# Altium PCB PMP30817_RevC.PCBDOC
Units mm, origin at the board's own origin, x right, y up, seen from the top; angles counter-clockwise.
Board outline 75.77 x 49.68 mm, 2 copper layers (Top Layer, Bottom Layer), stack 1.575 mm thick; 52 components, 29 nets, 115 pads, 20 vias.
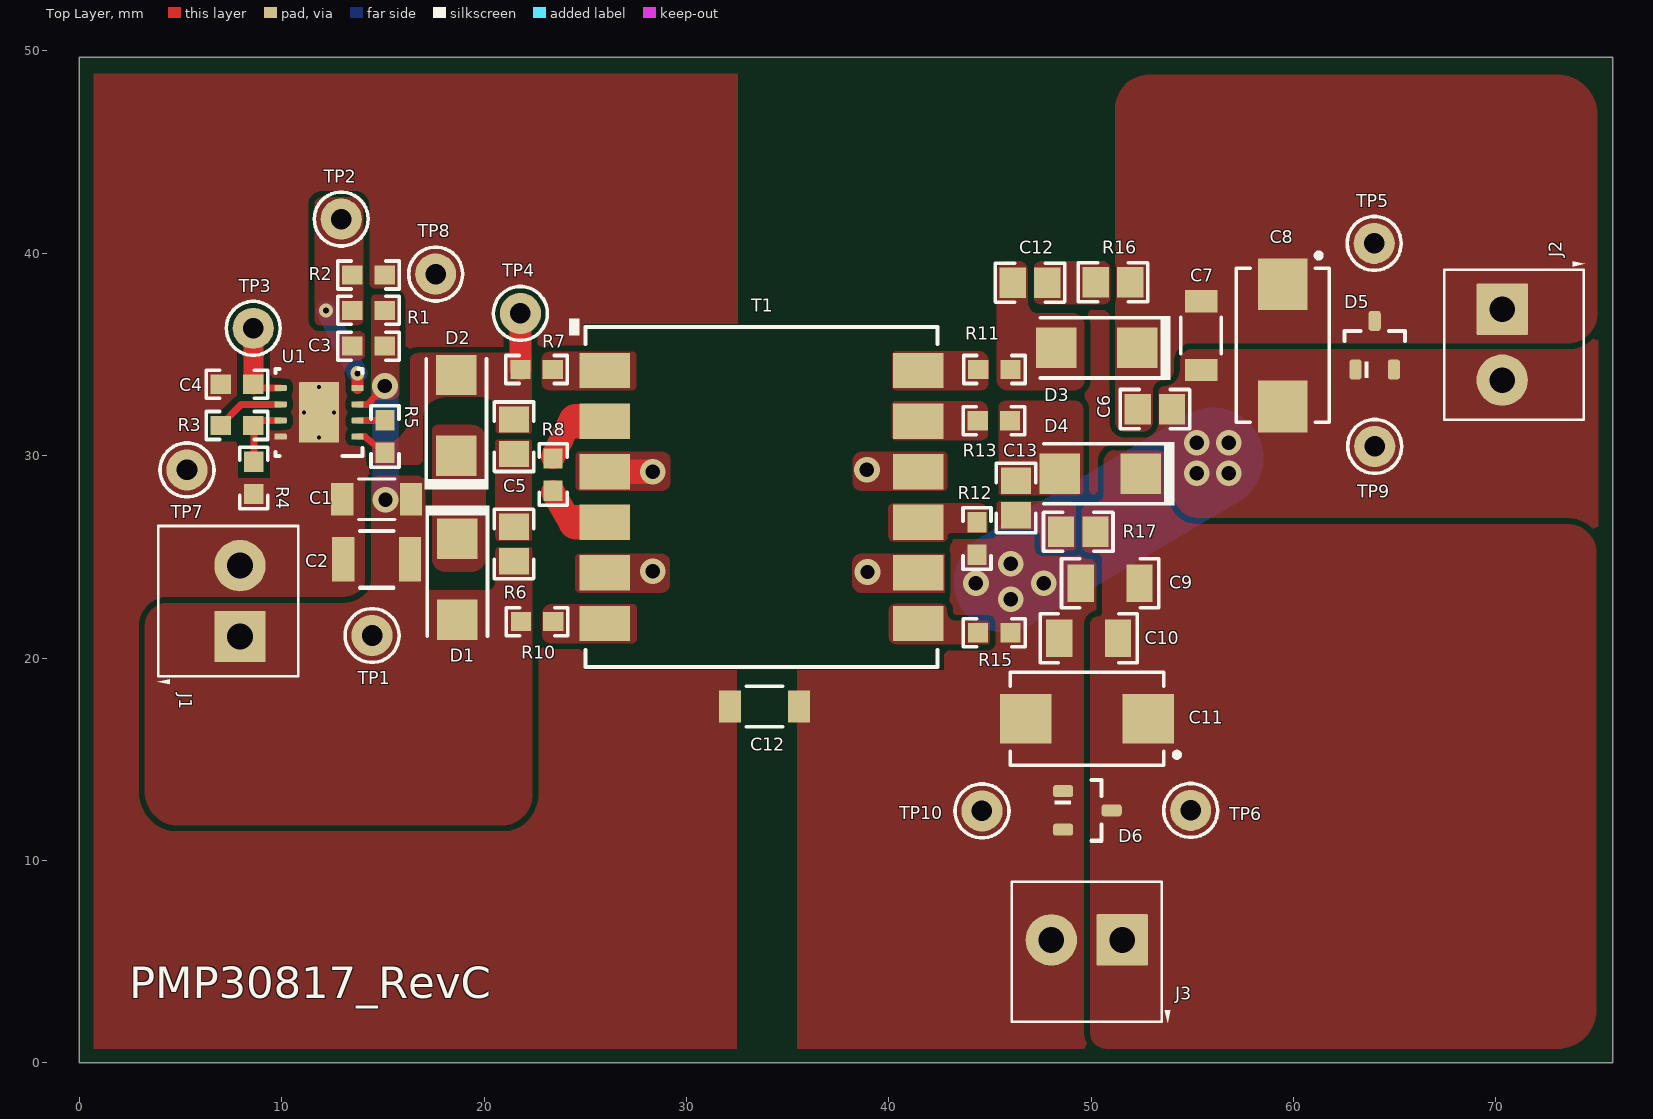
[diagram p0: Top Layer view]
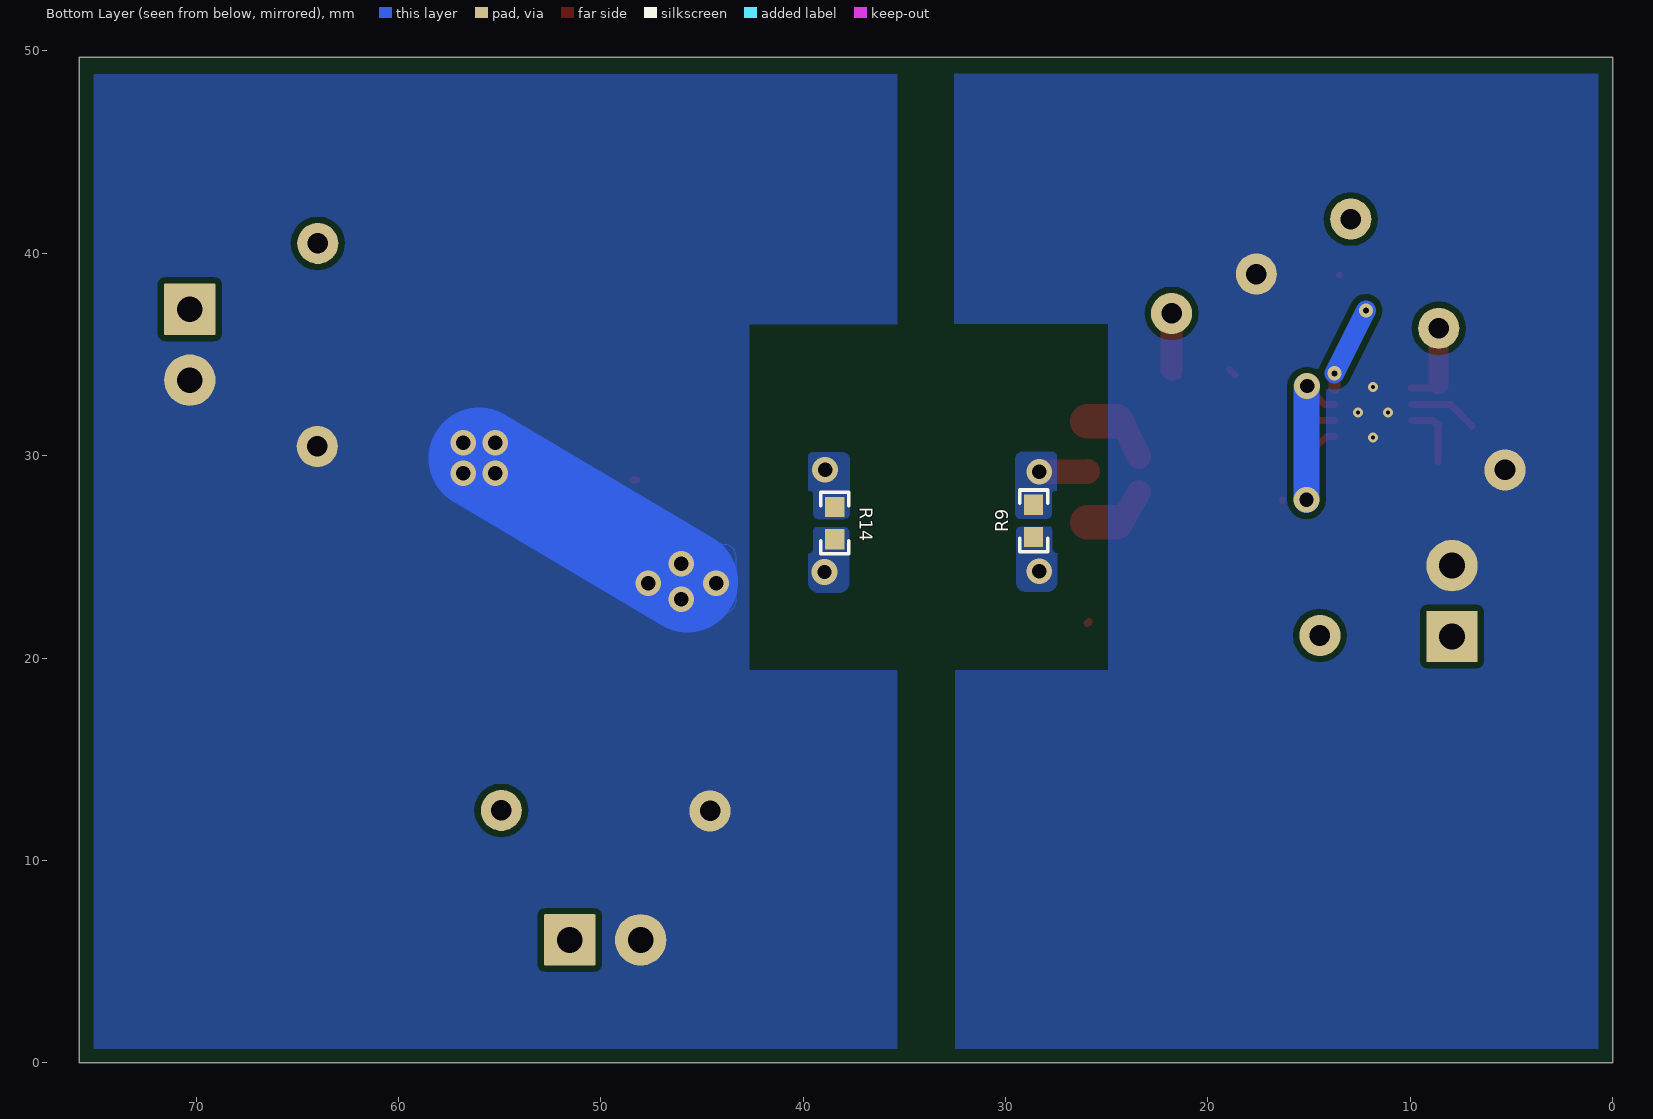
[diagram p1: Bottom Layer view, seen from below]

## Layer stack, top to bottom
Top Solder: solder mask 0.0102, Solder Resist, Dk 3.5
Top Layer: signal copper 0.0356
Dielectric1: core 1.5037, FR-4, Dk 4.8
Bottom Layer: signal copper 0.0356
Bottom Solder: solder mask 0.0102, Solder Resist, Dk 3.5

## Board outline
0,0 75.768,0 75.768,49.682 0,49.682

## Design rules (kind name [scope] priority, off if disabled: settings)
AcuteAngle [All] p1: minimum=4.50000000000000E+0001 checktracksonly=FALSE
AssemblyTestPointUsage [All] p1: valid=2
BoardOutlineClearance BoardOutlineClearance_MountingHoles [OnCopper and InComponentClass('Mounting Holes')] p1: gap=1 ignorepadtopadclearanceinfootprint=FALSE
BoardOutlineClearance BoardOutlineClearance_Poly [OnCopper and IsPoly] p2: gap=0.635 ignorepadtopadclearanceinfootprint=FALSE
BoardOutlineClearance [OnCopper and Not InComponentClass('Logo') and not InComponentClass('FiducialMark') and not InRegion(1000,500,4000,800) and not InPoly] p3: gap=1.905 ignorepadtopadclearanceinfootprint=FALSE
Clearance Clearance_Keepouts [((IsTrack Or IsArc) And Not InPoly) And IsFree and IsKeepOut vs ((IsTrack Or IsArc) And Not InPoly) And IsFree and IsKeepOut] p1: gap=0 ignorepadtopadclearanceinfootprint=FALSE
Clearance Clearance_Poly [InPolygon] p2: gap=0.3 ignorepadtopadclearanceinfootprint=TRUE
Clearance Clearance_FiducialMark [IsKeepOut and InComponentClass('FiducialMark') vs IsPad and InComponentClass('FiducialMark')] p3: gap=0 ignorepadtopadclearanceinfootprint=FALSE
Clearance [All] p4: gap=0.2 ignorepadtopadclearanceinfootprint=TRUE
ComponentClearance ComponentClearance_MountingHoles_FiducialMarks [InComponentClass('Mounting Holes') vs InComponentClass('FiducialMark')] p1: gap=1.27 collisioncheckmode=3 verticalgap=0.254 showdistances=FALSE
ComponentClearance ComponentClearance_Shunt [InComponentClass('Header') vs InComponentClass('Shunt')] p2: gap=0 collisioncheckmode=3 verticalgap=0 showdistances=FALSE
ComponentClearance ComponentClearance_Logo [InComponentClass('Logo')] p3: gap=1.27 collisioncheckmode=3 verticalgap=0.254 showdistances=FALSE
ComponentClearance ComponentClearance_ScrewToNut [(HasFootprint('NY PMS 440 0025 PH')) vs (HasFootprint('Keystone_1902C'))] p4: gap=0.127 collisioncheckmode=3 verticalgap=0.254 showdistances=FALSE
ComponentClearance ComponentClearance_MountingHoles [InComponentClass('Mounting Holes')] p5: gap=6.35 collisioncheckmode=3 verticalgap=2540 showdistances=FALSE
ComponentClearance ComponentClearance_SmallPassives [HasFootprint('0201*') or HasFootprint('0402*') or HasFootprint('0508') or HasFootprint('0603*') or HasFootprint('0612') or HasFootprint('0805*') or HasFootprint('0815*') or HasFootprint('0830*') or HasFootprint('1206*') or HasFootprint('1210*') or HasFootprint('1808*') or HasFootprint('1812*') or HasFootprint('1825*') or HasFootprint('2010*') or HasFootprint('2220*') or HasFootprint('2225*') or HasFootprint('2512*') or HasFootprint('2728*') or HasFootprint('3518*') vs HasFootprint('0201*') or HasFootprint('0402*') or HasFootprint('0508') or HasFootprint('0603*') or HasFootprint('0612') or HasFootprint('0805*') or HasFootprint('0815*') or HasFootprint('0830*') or HasFootprint('1206*') or HasFootprint('1210*') or HasFootprint('1808*') or HasFootprint('1812*') or HasFootprint('1825*') or HasFootprint('2010*') or HasFootprint('2220*') or HasFootprint('2225*') or HasFootprint('2512*') or HasFootprint('2728*') or HasFootprint('3518*')] p6: gap=0.38 collisioncheckmode=3 verticalgap=0.254 showdistances=FALSE
ComponentClearance ComponentClearance_THtoSMT [IsThruComponent vs IsSMTComponent] p7: gap=1.016 collisioncheckmode=3 verticalgap=0.762 showdistances=FALSE
ComponentClearance ComponentClearance_THtoTH [IsThruComponent vs IsThruComponent] p8: gap=0.762 collisioncheckmode=3 verticalgap=0.762 showdistances=FALSE
ComponentClearance [All] p9: gap=0.762 collisioncheckmode=3 verticalgap=0.254 showdistances=FALSE
DiffPairsRouting [All] p1: maxlimit=2.54 minlimit=0.254 mostfreqgap=0.254 toplayer_minwidth=0.381 toplayer_maxwidth=0.381 toplayer_prefwidth=0.381 bottomlayer_minwidth=0.381 bottomlayer_maxwidth=0.381 bottomlayer_prefwidth=0.381 maxuncoupledlength=25.4
FabricationTestPointUsage TestPointUsage [All] p1: valid=2 allowmultiple=FALSE
FabricationTestpoint Testpoint [All] p1: side=3 testpointundercomponent=TRUE minsize=1.016 maxsize=2.54 preferedsize=1.524 minholesize=0 maxholesize=1.016 preferedholesize=0.813 testpointgrid=0.025 allowsidetop=TRUE allowsidebottom=TRUE usegrid=TRUE gridtolerance=0
FanoutControl Fanout_LCC [IsLCC] p1: bgadir=Out bgaviamode=Centered fanoutstyle=Auto fanoutdirection=Alternating viagrid=0.025 // Fanout_LCC (Default Rule)
FanoutControl Fanout_BGA [IsBGA] p2: bgadir=Out bgaviamode=Centered fanoutstyle=Auto fanoutdirection=Alternating viagrid=0.025 // Fanout_BGA (Default Rule)
FanoutControl Fanout_Default [All] p4: bgadir=Out bgaviamode=Centered fanoutstyle=Auto fanoutdirection=Alternating viagrid=0.025 // Fanout_Default (Default Rule)
FanoutControl Fanout_Small [(CompPinCount < 5)] p5: bgadir=Out bgaviamode=Centered fanoutstyle=Auto fanoutdirection=OutThenIn viagrid=0.025 // Fanout_Small (Default Rule)
HoleSize [All] p1: absolutevalues=TRUE maxlimit=6.375 minlimit=0.2 maxpercent=80.000 minpercent=20.000
MinimumAnnularRing MinimumAnnularRing_ThermalPadVias [IsVia and InAnyComponent] p1: minimumring=0.15
MinimumAnnularRing [All] p2: minimumring=0.2
MinimumSolderMaskSliver MinimumSolderMaskSliver_Logo [InComponentClass('Logo') vs InComponentClass('Logo')] p1: minsoldermaskwidth=0.018
MinimumSolderMaskSliver [All] p2: minsoldermaskwidth=0.1
PlaneConnect [All] p1: planeconnectstyle=Relief reliefexpansion=0.254 reliefentries=4 reliefconductorwidth=0.254 reliefairgap=0.254
PolygonConnect [All] p1: connectstyle=Direct reliefconductorwidth=0.254 reliefentries=4 polygonreliefangle="90 Angle" airgapwidth=0.254
RoutingVias ThermalPadVias [IsVia and InAnyComponent] p1: holewidth=0.2 width=0.5 viastyle="Through Hole" minholewidth=0.2 minwidth=0.5 maxholewidth=0.33 maxwidth=0.6
RoutingVias [All] p2: holewidth=0.406 width=0.864 viastyle="Through Hole" minholewidth=0.2 minwidth=0.66 maxholewidth=1.016 maxwidth=1.651
SilkToBoardRegionClearance [Not ((IsComment or IsDesignator) And (Hide <> 'False')) and not InRegion(1000,500,4000,800)] p1:
SilkToSilkClearance SilkToSilkClearance_Pb-FreeLogo [(HasFootprint('Pb-Free_Overlay_Medium') OR HasFootprint('Pb-Free_Overlay_Small')) vs (HasFootprint('Pb-Free_Overlay_Medium') OR HasFootprint('Pb-Free_Overlay_Small'))] p1 off: silktosilkclearance=0
SilkToSilkClearance [All] p2 off: silktosilkclearance=0.1
SilkToSolderMaskClearance SilkToComponentPadClearance [(IsPad or IsFill or IsRegion) and InAnycomponent] p1 off: minsilkscreentomaskgap=0.127 clearancetoexposedcopper=TRUE
SilkToSolderMaskClearance "Silk to Solder Mask Opening" [All] p2 off: minsilkscreentomaskgap=0.1 clearancetoexposedcopper=FALSE
SolderMaskExpansion [All] p1: expansion=0.05
UnRoutedNet [All] p1: checkbadconnections=TRUE
Width [All] p1: maxlimit=10 minlimit=0.152 preferedwidth=0.35 checkconnectedcopper=TRUE
14 further rules are at their usual default settings.

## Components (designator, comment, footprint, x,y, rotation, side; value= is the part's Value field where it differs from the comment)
C1 "C3216X7R1H475K160AC" 1206_180 14.696,27.844 r180 top value=4.7uF
C2 "C1210C475K5RACAUTO" 1210_280 14.696,24.872 r180 top value=4.7uF
C3 "C0603C104K5RACAUTO" 0603 14.29,35.413 r180 top value=0.1uF
C4 "C1608X7R1H473K080AA" 0603 7.796,33.521 r180 top value=0.047uF
C5 "08055A220JAT2A" 0805 21.478,30.934 r90 top value=22pF
C6 "GRM21BR61A476ME15L" 0805 53.143,32.298 r0 top value=47uF
C7 "C3216X5R1A476M160AB" 1206_180 55.429,35.93 r270 top value=DNP
C8 "T495D336K025ATE090" 7343-31 59.461,35.45 r270 top value=33uF
C9 "GRM31CR61E476ME44L" 1206 50.933,23.694 r180 top value=47uF
C10 "GRM31CR61E476ME44L" 1206 49.872,20.976 r180 top value=DNP
C11 "T495D336K025ATE090" 7343-31 49.794,16.993 r180 top value=33uF
C12 "C1206C102KGRACAUTO" 1206_180 33.858,17.602 r180 top value=1000pF
C12 "08055A220JAT2A" 0805 46.973,38.546 r180 top value=22pF
C13 "08051A220JAT2A" 0805 46.285,27.91 r90 top value=22pF
D1 "CMZ5938B" SMA 18.684,23.881 r270 top value=36V
D2 "MBRA140T3G" SMA 18.633,31.984 r90 top value=40V
D3 "MBRA130LT3G" SMA 50.271,35.321 r180 top value=30V
D4 "MBRA160T3G" SMA 50.45,29.104 r180 top value=60V
D5 "BZX84B8V2LT1G" SOT-23 64.008,35.456 r90 top value=8.2V
D6 "MMBZ5245BLT1G" SOT-23 49.81,12.471 r0 top value=15V
J1 "ED555/2DS" TERM_BLK_ED555-2DS 7.94,21.062 r90 top
J2 "ED555/2DS" TERM_BLK_ED555-2DS 70.307,37.236 r270 top
J3 "ED555/2DS" TERM_BLK_ED555-2DS 51.537,6.071 r180 top
R1 "RC0603FR-07536KL" 0603 14.29,37.175 r0 top value=536k
R2 "RC0603FR-07100KL" 0603 14.29,38.927 r180 top value=100k
R3 "RC0603FR-07210KL" 0603 7.796,31.489 r180 top value=210k
R4 "RC0603FR-0712K1L" 0603 8.626,28.898 r90 top value=12.1k
R5 "RT0603BRD07169KL" 0603 15.103,30.942 r270 top value=169k
R6 "RG2012P-101-B-T5" 0805 21.478,25.634 r270 top value=100
R7 "RK73H1JT" 0603 22.596,34.254 r0 top value=10.0
R8 "RK73H1JT" 0603 23.408,29.063 r270 top value=10.0
R9 "RK73H1JT" 0603 28.615,26.778 r270 bottom value=10.0
R10 "RK73H1JTL" 0603 22.621,21.798 r0 top value=10.0
R11 "RK73H1JT" 0603 45.218,34.254 r0 top value=10.0
R12 "RK73H1JT" 0603 44.354,25.903 r270 top value=10.0
R13 "RK73H1JT" 0603 45.192,31.725 r0 top value=10.0
R14 "RK73H1JT" 0603 38.436,26.665 r270 bottom value=10.0
R15 "RK73H1JT" 0603 45.21,21.249 r0 top value=10.0
R16 "RG2012P-101-B-T5" 0805 51.072,38.564 r0 top value=100
R17 "RG2012P-101-B-T5" 0805 49.358,26.234 r0 top value=100
T1 "749196241" WURTH_749196211 33.713,27.956 r0 top value=6.8uH
TP1 "5000" Keystone5000 14.468,21.113 r180 top
TP2 "5000" Keystone5000 12.944,41.687 r270 top
TP3 "5000" Keystone5000 8.596,36.29 r270 top
TP4 "5000" Keystone5000 21.796,37.026 r90 top
TP5 "5000" Keystone5000 63.983,40.488 r180 top
TP6 "5000" Keystone5000 54.915,12.471 r180 top
TP7 "5001" Keystone5001 5.324,29.295 r90 top
TP8 "5001" Keystone5001 17.608,38.969 r90 top
TP9 "5001" Keystone5001 64.008,30.455 r0 top
TP10 "5001" Keystone5001 44.602,12.446 r0 top
U1 "LM5180NGUR" NGU0008C 11.851,32.136 r180 top

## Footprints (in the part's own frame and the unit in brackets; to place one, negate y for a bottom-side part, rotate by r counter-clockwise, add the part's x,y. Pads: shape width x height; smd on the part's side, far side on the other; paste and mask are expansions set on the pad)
0603 [mm] "0603 from SM-752 data"
  rect 1x0.95 smd: 1(-0.8,0) 2(0.8,0)
  silkscreen extent -1.52,-0.69 1.52,0.69, body extent -0.87,-0.47 0.87,0.47, height 1
0805 [mm] "0805 from SM-752 data"
  rect 1.3x1.5 smd: 1(-0.85,0) 2(0.85,0)
  silkscreen extent -1.72,-0.97 1.72,0.97, body extent -1.1,-0.72 1.1,0.72, height 1.45
1206 [mm] "1206 from SM-752 data"
  rect 1.3x1.85 smd: 1(-1.45,0) 2(1.45,0)
  silkscreen extent -2.4,-1.21 2.4,1.21, body extent -1.7,-0.9 1.7,0.9, height 1.35
1206_180 [mm] "1206_180"
  rect 1.1x1.6 smd: 1(-1.7,0) 2(1.7,0)
  silkscreen extent -0.9,-1 0.9,1, body extent -1.75,-0.95 1.75,0.95, height 1.8
1210_280 [mm] "SMD, 2-Leads, Body 3.6x2.8mm, Height 2.8mm"
  rect 1.1x2.2 smd: 1(-1.65,0) 2(1.65,0)
  silkscreen extent -0.84,-1.4 0.84,1.4, body extent -1.8,-1.4 1.8,1.4, height 2.8
7343-31 [mm] "Medium Density based on Kemet T495 dimensions"
  rect 2.55x2.45 smd: 1(-3.025,0) 2(3.025,0)
  silkscreen extent -4.56,-2.3 3.8,2.3, body extent -3.8,-2.3 3.8,2.3, height 3.1
Keystone5000 [mil] "For Keystone 500x miniature loop terminals"
  round 80 hole 40: 1(0,0)
  silkscreen extent -52,-52 52,52, body extent -49,-49 49,49, height 182
Keystone5001 [mil] "For Keystone 500x miniature loop terminals"
  round 80 hole 40: 1(0,0)
  silkscreen extent -52,-52 52,52, body extent -49,-49 49,49, height 182
NGU0008C [mm] "SON, 8-Leads, Body 4x4mm, Pitch 0.8mm"
  rrect33% 0.6x0.3 smd: 1(-1.9,1.2) 2(-1.9,0.4) 3(-1.9,-0.4) 4(-1.9,-1.2) 5(1.9,-1.2) 6(1.9,-0.4) 7(1.9,0.4) 8(1.9,1.2)
  rrect8% 1.75x1.31 on Top Paste: 9(0,0.755) 9(0,-0.755)
  rrect5% 1.98x3 smd paste-1.5: 9(0,0)
  silkscreen extent -2.15,-2.15 2.15,2.15, body extent -2,-2 2,2, height 0.77
SMA [mm] "Molded Diode, 2-Leads, Body 4.3x2.6mm, IPC Medium Density, based on OnSemi component dimensions and land pattern"
  rect 2x2 smd: 1(-2,0) 2(2,0)
  silkscreen extent -3.66,-1.57 2.79,1.57, body extent -2.6,-1.3 2.6,1.3, height 2.42
SOT-23 [mm] "SOT23, 3-Leads, Body 2.9x1.3mm, Pitch 0.95mm, Lead Span 2.5mm, IPC Medium Density"
  rrect50% 1x0.6 smd: 1(-1.2,0.95) 2(-1.2,-0.95) 3(1.2,0)
  silkscreen extent -1.62,-1.5 0.7,1.5, body extent -1.16,-1.45 1.21,1.45, height 1
TERM_BLK_ED555-2DS [mil]
  rrect4% 100x100 hole 50: 1(0,0)
  round 100 hole 50: 2(138,0)
  silkscreen extent -93,-113 215,161, body extent -69,-150 207,106, height 323
WURTH_749196211 [mm] "Wurth"
  rect 2.5x1.75 smd: 1(-7.75,6.25) 2(-7.75,3.75) 3(-7.75,1.25) 4(-7.75,-1.25) 5(-7.75,-3.75) 6(-7.75,-6.25) 7(7.75,-6.25) 8(7.75,-3.75) 9(7.75,-1.25) 10(7.75,1.25) 11(7.75,3.75) 12(7.75,6.25)
  silkscreen extent -9.5,-8.4 8.69,8.8, body extent -8.4,-8.15 8.4,8.15, height 7.42

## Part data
C1: library part CMP-0008702-1, "CAP, CERM, 4.7 uF, 50 V, +/- 10%, X7R, 1206", Cap_Case=1206_180, Manufacturer=TDK, Supplier Part Number 1=445-8032-1-ND, TempCo=X7R, Tolerance_%=10%, Value1="0.003158 ohm", Value2=50V, ValueDisplayed=4.7uF
C2: library part CMP-0079604-1, "CAP, CERM, 4.7 µF, 50 V,+/- 10%, X7R, AEC-Q200 Grade 1, 1210", Cap_Case=1210, Manufacturer=Kemet, PartNumber=DNP, Supplier Part Number 1=399-7049-1-ND, TempCo=X7R, Tolerance_%=10%, Value2=50V
C3: library part CMP-0079602-1, "CAP, CERM, 0.1 µF, 50 V,+/- 10%, X7R, AEC-Q200 Grade 1, 0603", Cap_Case=0603, Manufacturer=Kemet, Supplier Part Number 1=399-6856-1-ND, TempCo=X7R, Tolerance_%=10%, Value2=50V, ValueDisplayed=0.1µF
C4: library part CMP-0007049-1, "CAP, CERM, 0.047 uF, 50 V, +/- 10%, X7R, 0603", Cap_Case=0603, Manufacturer=TDK, Supplier Part Number 1=445-1313-1-ND, TempCo=X7R, Tolerance_%=10%, Value1="0.049007 ohm", Value2=50V, ValueDisplayed=0.047uF
C5 C12: library part CMP-0007599-1, "CAP, CERM, 22 pF, 50 V, +/- 5%, C0G/NP0, 0805", Cap_Case=0805, Manufacturer=AVX, Supplier Part Number 1=478-1308-1-ND, TempCo=C0G/NP0, Tolerance_%=5%, Value1="0.92 ohm", Value2=50V, ValueDisplayed=22pF
C6: library part CMP-0078699-1, "CAP, CERM, 47 µF, 10 V,+/- 20%, X5R, 0805", Cap_Case=0805, Manufacturer=MuRata, Supplier Part Number 1=490-9961-1-ND, TempCo=X5R, Tolerance_%=20%, Value2=10V, ValueDisplayed=47µF
C7: library part CMP-0008650-1, "CAP, CERM, 47 uF, 10 V, +/- 20%, X5R, 1206", Cap_Case=1206, Manufacturer=TDK, PartNumber=47µF, Supplier Part Number 1=445-6006-1-ND, TempCo=X5R, Tolerance_%=20%, Value1=Unknown, Value2=10V, ValueDisplayed=DNP
C8 C11: library part CMP-0011771-2, "CAP, TA, 33 uF, 25 V, +/- 10%, 0.09 ohm, SMD", Cap_Case=D, Manufacturer=Kemet, Supplier Part Number 1=399-4785-1-ND, Tolerance_%=10%, Value1="0.09 ohm", Value2=25V, ValueDisplayed=DNP
C9: library part CMP-0008646-1, "CAP, CERM, 47 uF, 25 V, +/- 20%, JB, 1206", Cap_Case=1206, Manufacturer=TDK, Supplier Part Number 1=445-11717-1-ND, TempCo=JB, Tolerance_%=20%, Value1=Unknown, Value2=25V, ValueDisplayed=100uF
C10: library part CMP-0008646-1, "CAP, CERM, 47 uF, 25 V, +/- 20%, JB, 1206", Cap_Case=1206, Manufacturer=TDK, PartNumber=DNP, Supplier Part Number 1=445-11717-1-ND, TempCo=JB, Tolerance_%=20%, Value1=Unknown, Value2=25V
C12: library part CMP-0008579-1, "CAP, CERM, 1000 pF, 2000 V, +/- 10%, X7R, AEC-Q200 Grade 1, 1206", Cap_Case=1206, Manufacturer=Kemet, Supplier Part Number 1=399-12976-1-ND, TempCo=X7R, Tolerance_%=10%, Value1=Unknown, Value2=2000V, ValueDisplayed=1000pF
C13: library part CMP-0007524-1, "CAP, CERM, 22 pF, 100 V, +/- 5%, C0G/NP0, 0805", Cap_Case=0805, Manufacturer=AVX, Supplier Part Number 1=478-1280-1-ND, TempCo=C0G/NP0, Tolerance_%=5%, Value1="0.92 ohm", Value2=100V, ValueDisplayed=22pF
D1: library part CMP-0082174-1, "Diode, Zener, 36V, 1.5 W, SMA", Manufacturer="Taiwan Semiconductor", Power_W=1.5W, Value1=1.25W
D2: library part CMP-0028550-1, "Diode, Schottky, 40 V, 1 A, SMA", Manufacturer="ON Semiconductor", Supplier Part Number 1=MBRA140T3GOSCT-ND, Value1=1A, Value2=0.55V
D3: library part CMP-0028549-1, "Diode, Schottky, 30 V, 1 A, SMA", Manufacturer="ON Semiconductor", Supplier Part Number 1=MBRA130LT3GOSCT-ND, Value1=1A, Value2=0.41V
D4: library part CMP-0028551-1, "Diode, Schottky, 60 V, 1 A, SMA", Manufacturer="ON Semiconductor", Supplier Part Number 1=MBRA160T3GOSCT-ND, Value1=1A, Value2=0.51V
D5: library part CMP-0005972-1, "Diode, Zener, 8.2 V, 225 mW, SOT-23", Manufacturer="ON Semiconductor", Power_W=225mW, Supplier Part Number 1=BZX84B8V2LT1GOSCT-ND, Value1=0.225W
D6: library part CMP-0005953-1, "Diode, Zener, 15 V, 225 mW, SOT-23", Manufacturer="ON Semiconductor", Power_W=225mW, Supplier Part Number 1=MMBZ5245BLT1GOSCT-ND, Value1=0.225W
J1 J2 J3: library part CMP-0074913-1, "Terminal Block, 3.5mm Pitch, 2x1, TH", Color=Grey, Current_A=6A, Manufacturer="On-Shore Technology", Supplier Part Number 1=ED1514-ND, Voltage_V=150V
R1: library part CMP-0023174-4, "RES, 536 k, 1%, 0.1 W, 0603", Manufacturer=Yageo, Power_W=100mW, Supplier Part Number 1=311-536KHRCT-ND, TempCo="100 ppm/C", Tolerance_%=1%, Value2=0.1W, Value_Code=536k
R2: library part CMP-0022735-5, "RES, 100 k, 1%, 0.1 W, 0603", Manufacturer=Yageo, Power_W=100mW, Supplier Part Number 1=311-100KHRCT-ND, TempCo="100 ppm/C", Tolerance_%=1%, Value2=0.1W, Value_Code=100k
R3: library part CMP-0022909-4, "RES, 210 k, 1%, 0.1 W, 0603", Manufacturer=Yageo, Power_W=100mW, Supplier Part Number 1=311-210KHRCT-ND, TempCo="100 ppm/C", Tolerance_%=1%, Value2=0.1W, Value_Code=210k
R4: library part CMP-0022776-5, "RES, 12.1 k, 1%, 0.1 W, 0603", Manufacturer=Yageo, Power_W=100mW, Supplier Part Number 1=311-12.1KHRCT-ND, TempCo="100 ppm/C", Tolerance_%=1%, Value2=0.1W, Value_Code=12k1, ValueDisplayed=12.1k
R5: library part CMP-0023796-2, "RES, 169 k, 0.1%, 0.1 W, 0603", Manufacturer="Yageo America", Power_W=100mW, TempCo="25 ppm/C", Tolerance_%=0.1%, Value2=0.1W, Value_Code=169k
R6 R16 R17: library part CMP-0018851-1, "RES, 100, 0.1%, 0.125 W, 0805", Manufacturer="Susumu Co Ltd", Power_W=125mW, Supplier Part Number 1=RG20P100BCT-ND, TempCo="25 ppm/C", Tolerance_%=0.1%, Value2=0.125W, Value_Code=100R, ValueDisplayed=100
R7 R8 R9 R11 R12 R13 R14 R15: library part CMP-0023661-1, "RES, 0, 1%, 0.1 W, 0603", Manufacturer="Yageo America", PartNumber=RK73H1JTL, Power_W=100mW, TempCo="25 ppm/C", Tolerance_%=0.1%, Value2=0.1W, Value_Code=10R0, ValueDisplayed=0
R10: library part CMP-0023661-1, "RES, 0, 1%, 0.1 W, 0603", Manufacturer="Yageo America", Power_W=100mW, TempCo="25 ppm/C", Tolerance_%=0.1%, Value2=0.1W, Value_Code=10R0, ValueDisplayed=0
T1: library part CMP-0030531-1, "Transformer, 21.6uH, SMT", Manufacturer="Wurth Elektronik", ValueDisplayed=6.8uH
TP1 TP2 TP3 TP4 TP5 TP6: library part CMP-0055137-1, "Test Point, Miniature, Red, TH", Color=Red, Manufacturer=Keystone, Supplier Part Number 1=36-5000-ND
TP7 TP8 TP9 TP10: library part CMP-0055138-1, "Test Point, Miniature, Black, TH", Color=Black, Manufacturer=Keystone, Supplier Part Number 1=36-5001-ND
U1: library part CMP-0084791-1, "70-VIN PSR Flyback DC/DC Converter With 100-V, 1.5-A Integrated Power MOSFET, NGU0008C (WSON-8)", Alternate Manufacturer="Texas Instruments", Alternate PartNumber=LM5180NGUT

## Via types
v1: diameter 1.27, hole 0.711, Top Layer to Bottom Layer, 14 vias
v2: diameter 0.5, hole 0.2, Top Layer to Bottom Layer, 4 vias
v3: diameter 0.7, hole 0.3, Top Layer to Bottom Layer, 2 vias

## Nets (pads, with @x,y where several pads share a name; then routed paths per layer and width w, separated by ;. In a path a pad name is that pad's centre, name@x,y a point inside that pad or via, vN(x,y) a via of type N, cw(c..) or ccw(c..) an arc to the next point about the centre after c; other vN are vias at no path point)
GND: C1.2 C2.2 C3.2 C4.2 C12.2@32.158,17.602 J1.2 R2.1 R4.1 TP7.1 TP8.1 U1.8 U1.9@11.851,32.136
  other v2: 11.851,30.886 11.111,32.136 12.591,32.136 11.851,33.386
NetC1_1: C1.1 C2.1 C3.1 D1.2 J1.1 R1.2 R6.2 R10.1 TP1.1 U1.3 | length 7.5
  Top Layer w0.35: U1.3 14.239,32.536 v1(15.103,33.441) ; TP1.1@14.417,21.062 TP1.1 ; C1.1@16.322,27.818 C1.1@16.346,27.794
  Bottom Layer w0.35: v1(15.103,33.441) v1@15.128,33.416
  Bottom Layer w1.3: v1(15.128,27.818) v1@15.128,33.416
NetC4_1: C4.1 TP3.1 U1.5 | length 4
  Top Layer w0.35: TP3.1 TP3.1@8.602,36.283 ; C4.1@8.671,33.33 U1.5
  Top Layer w1: C4.1@8.602,33.528 TP3.1@8.602,36.283
NetC5_1: C5.1 R6.1
NetC5_2: C5.2 D2.2 R5.2 R7.1 TP4.1 U1.1 | length 5.3
  Top Layer w0.35: U1.1 14.106,30.936 R5.2 ; D2.2@18.659,33.984 D2.2@18.929,34.254 ; R7.1@21.478,33.936 R7.1 ; TP4.1 TP4.1@21.834,37.064
  Top Layer w1.1: R7.1 TP4.1
NetC6_1: C6.1 C7.1 C8.1 D3.1 D5.3 J2.1 R16.2 TP5.1
NetC9_1: C9.1 C10.1 C11.1 D4.1 D6.3 J3.1 R17.2 TP6.1
NetC12_1: C12.1@47.823,38.546 R16.1
NetC12_2: C12.2@46.123,38.546 D3.2 R11.2
NetC13_1: C13.1 R17.1
NetC13_2: C13.2 D4.2 R13.2 | length 0.2
  Top Layer w0.35: D4.2@48.218,28.789 D4.2@48.44,28.789
NetD1_1: D1.1 D2.1
NetR1_1: R1.1 R2.2 TP2.1 U1.4 | length 4.2
  Top Layer w0.6: U1.4 v3(13.751,34.067)
  Bottom Layer w1: v3(12.192,37.175) v3(13.751,34.067)
NetR3_1: R3.1 R4.2 U1.7 | length 3.2
  Top Layer w0.35: R3.1@8.594,31.493 8.88,31.73 U1.7 ; R4.2 R3.1@8.626,31.461
NetR3_2: R3.2 U1.6 | length 3.4
  Top Layer w0.35: R3.2@6.946,31.471 7.999,32.525 U1.6
NetR5_1: R5.1 U1.2 | length 1.4
  Top Layer w0.35: U1.2 15.096,31.736 R5.1
NetR7_2: R7.2 T1.1
NetR8_1: R8.1 T1.2 | length 3.5
  Top Layer w1.2: R8.1@23.408,29.937 24.323,31.842
  Top Layer w1.7: 24.535,31.696 T1.2
NetR8_2: R8.2 T1.4 | length 3.3
  Top Layer w1.2: R8.2@23.408,28.188 24.348,26.557
  Top Layer w1.7: 24.526,26.701 T1.4
NetR9_1: R9.1 T1.3 | length 2.4
  Top Layer w1.2: v1(28.336,29.206) T1.3 ; T1.3 25.938,29.231 T1.3
NetR9_2: R9.2 T1.5
  other v1: 28.336,24.288
NetR10_2: R10.2 T1.6 | length 0.2
  Top Layer w0.35: T1.6@25.87,21.798 T1.6 ccw(c25.893,21.636) T1.6@25.893,21.735
NetR11_1: R11.1 T1.12
NetR12_1: R12.1 T1.9
NetR13_1: R13.1 T1.11
NetR14_1: R14.1 T1.10
  other v1: 38.919,29.307
NetR14_2: R14.2 T1.8
  other v1: 38.944,24.252
NetR15_1: R15.1 T1.7
S-GND: C6.2 C7.2 C8.2 C9.2 C10.2 C11.2 C12.1@35.558,17.602 D5.1 D5.2 D6.1 D6.2 J2.2 J3.2 R12.2 R15.2 TP9.1 TP10.1 | length 12
  Bottom Layer w5: 45.714,23.766 56.007,29.87
  other v1: 46.031,22.906 44.303,23.694 47.656,23.694 46.031,24.659 55.22,29.134 56.794,29.134 55.22,30.632 56.794,30.632
pads on no net: U1.9@11.851,31.381 U1.9@11.851,32.891

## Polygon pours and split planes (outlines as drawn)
no net on Top Layer "TOP_LAYER_NONET_P364" (solid, remove dead copper, pour order 364): -0.747,48.799
NetC13_1 on Top Layer "TOP_LAYER_NETC13_1_P362" (solid, remove dead copper, pour order 362): 48.965,27.737 cw(c48.965,27.477) 49.149,27.661 cw(c48.965,27.477) 49.225,27.477 49.225,25.438 cw(c49.135,25.438) 49.199,25.375 cw(c49.076,25.497) 49.076,25.324 47.674,25.324 cw(c47.674,25.537) 47.523,25.386 cw(c47.623,25.485) 47.482,25.485 47.482,25.999 ccw(c47.157,25.999) 47.387,26.229 47.345,26.27 ccw(c47.178,26.102) 47.178,26.34 45.493,26.34 cw(c45.493,26.513) 45.371,26.391 cw(c45.447,26.467) 45.339,26.467 45.339,27.623 cw(c45.447,27.623) 45.371,27.7 cw(c45.46,27.61) 45.46,27.737
NetC13_2 on Top Layer "TOP_LAYER_NETC13_2_P046" (solid, remove dead copper, pour order 46): 46.355,32.699 49.225,32.699 cw(c49.225,32.321) 49.492,32.588 cw(c49.218,32.313) 49.606,32.313 49.606,28.287 cw(c49.374,28.27) 49.531,28.098 cw(c49.403,28.231) 49.399,28.046 45.593,28.046 cw(c45.592,28.226) 45.466,28.098 cw(c45.585,28.204) 45.426,28.213 45.426,32.394 cw(c45.736,32.394) 45.517,32.614 cw(c45.734,32.381) 45.745,32.699 45.923,32.699
NetC1_1 on Top Layer "TOP_LAYER_NETC1_1_P188" (solid, remove dead copper, pour order 188): 22.392,25.359 ccw(c22.219,25.359) 22.342,25.481 ccw(c22.267,25.407) 22.267,25.512 20.767,25.512 ccw(c20.767,25.357) 20.656,25.467 20.646,25.456 ccw(c20.844,25.258) 20.564,25.257 20.564,23.817 cw(c20.044,23.817) 20.411,23.449 cw(c20.166,23.694) 20.166,23.348 17.424,23.348 cw(c17.424,23.695) 17.179,23.449 cw(c17.42,23.684) 17.084,23.688 17.084,28.58 ccw(c16.63,28.589) 16.957,28.904 ccw(c16.675,28.591) 16.652,29.012 14.823,29.012 ccw(c14.823,28.645) 14.563,28.904 14.544,28.885 ccw(c14.85,28.579) 14.417,28.578 14.417,23.809 cw(c13.55,23.808) 14.163,23.195 cw(c12.998,24.36) 12.998,22.713 4.231,22.713 ccw(c4.402,21.565) 3.469,22.256 ccw(c4.307,21.592) 3.245,21.469 3.245,13.311 ccw(c4.929,13.398) 3.8,12.146 ccw(c4.799,13.171) 4.817,11.74 20.929,11.74 ccw(c20.929,13.128) 21.91,12.146 ccw(c20.745,13.311) 22.392,13.311
NetR10_2 on Top Layer "TOP_LAYER_NETR10_2_P178" (solid, remove dead copper, pour order 178): 27.551,20.954 cw(c27.336,20.954) 27.336,20.739 23.297,20.739 cw(c23.297,21.165) 22.871,21.165 22.871,22.216 cw(c23.31,22.216) 23.31,22.655 27.344,22.655 cw(c27.344,22.448) 27.551,22.448
NetC5_2 on Top Layer "TOP_LAYER_NETC5_2_P156" (solid, remove dead copper, pour order 156): 22.36,31.244 cw(c22.114,31.244) 22.288,31.069 cw(c22.204,31.154) 22.204,31.035 20.741,31.035 cw(c20.741,31.178) 20.64,31.077 20.622,31.095 cw(c20.715,31.188) 20.583,31.188 20.583,32.238 ccw(c19.918,32.238) 20.388,32.708 20.386,32.711 ccw(c19.933,32.258) 19.933,32.898 18.138,32.898 ccw(c18.138,31.623) 17.236,32.525 ccw(c17.849,31.911) 16.982,31.911 16.982,29.867 cw(c16.635,29.867) 16.881,29.622 cw(c16.697,29.806) 16.697,29.545 14.671,29.545 cw(c14.671,29.699) 14.562,29.59 14.506,29.647 cw(c14.597,29.739) 14.468,29.739 14.468,30.485 cw(c14.659,30.485) 14.524,30.62 14.544,30.641 cw(c14.722,30.463) 14.722,30.714 15.359,30.714 ccw(c15.359,31.301) 15.774,30.886 15.939,31.051 ccw(c14.955,32.035) 16.346,32.035 16.346,34.708 cw(c16.696,34.708) 16.449,34.956 cw(c16.755,34.649) 16.755,35.083 22.04,35.083 cw(c22.04,34.728) 22.291,34.979 cw(c22.123,34.811) 22.36,34.811
NetC1_1 on Top Layer "TOP_LAYER_NETC1_1_P186" (solid, remove dead copper, pour order 186): 15.813,33.117 cw(c15.468,33.117) 15.712,32.873 cw(c15.467,33.118) 15.467,32.771 14.671,32.771 cw(c14.671,32.955) 14.541,32.825 14.493,32.873 cw(c14.677,33.057) 14.417,33.057 14.417,37.716 cw(c14.677,37.716) 14.493,37.9 cw(c14.621,37.772) 14.621,37.953 15.531,37.953 cw(c15.531,37.661) 15.738,37.867 cw(c15.555,37.684) 15.813,37.684
NetR1_1 on Top Layer "TOP_LAYER_NETR1_1_P154" (solid, remove dead copper, pour order 154): 14.036,36.678 cw(c13.862,36.678) 13.985,36.556 cw(c13.74,36.801) 13.74,36.454 11.851,36.454 cw(c11.851,36.638) 11.721,36.508 11.699,36.53 cw(c11.883,36.714) 11.623,36.714 11.623,42.449 cw(c11.868,42.449) 11.695,42.622 11.724,42.652 cw(c12.031,42.345) 12.031,42.779 13.602,42.779 cw(c13.602,42.345) 13.909,42.652 cw(c13.602,42.345) 14.036,42.345
NetC5_1 on Top Layer "TOP_LAYER_NETC5_1_P122" (solid, remove dead copper, pour order 122): 22.231,30.79 cw(c22.231,30.67) 22.316,30.755 cw(c22.194,30.632) 22.367,30.632 22.367,25.934 cw(c22.194,25.934) 22.316,25.812 cw(c22.255,25.873) 22.255,25.786 20.701,25.786 cw(c20.701,25.873) 20.64,25.812 cw(c20.824,25.996) 20.564,25.996 20.564,30.678 cw(c20.65,30.678) 20.589,30.739 cw(c20.712,30.617) 20.712,30.79
GND on Top Layer "TOP_LAYER_GND_P356" (solid, remove dead copper, pour order 356): 32.527,48.875 32.527,36.505 24.932,36.505 24.917,19.406 32.487,19.406 32.487,0.691 0.727,0.691 0.727,48.875
NetR7_2 on Top Layer "TOP_LAYER_NETR7_2_P110" (solid, remove dead copper, pour order 110): 27.526,33.441 cw(c27.31,33.441) 27.31,33.226 23.272,33.226 cw(c23.272,33.652) 22.845,33.652 22.845,34.703 cw(c23.284,34.703) 23.284,35.142 27.319,35.142 cw(c27.319,34.935) 27.526,34.935
NetR9_2 on Top Layer "TOP_LAYER_NETR9_2_P350" (solid, remove dead copper, pour order 350): 24.505,24.935 cw(c24.721,24.935) 24.721,25.151 28.759,25.151 cw(c28.759,24.725) 29.186,24.725 29.186,23.673 cw(c28.747,23.673) 28.747,23.234 24.713,23.234 cw(c24.713,23.442) 24.505,23.442
NetR9_1 on Top Layer "TOP_LAYER_NETR9_1_P342" (solid, remove dead copper, pour order 342): 24.526,29.977 cw(c24.742,29.977) 24.742,30.193 28.78,30.193 cw(c28.78,29.767) 29.207,29.767 29.207,28.715 cw(c28.768,28.715) 28.768,28.276 24.733,28.276 cw(c24.733,28.484) 24.526,28.484
NetD1_1 on Top Layer "TOP_LAYER_NETD1_1_P340" (solid, remove dead copper, pour order 340): 19.319,31.527 cw(c19.353,30.751) 19.878,31.323 cw(c19.304,30.795) 20.083,30.762 20.083,24.978 cw(c19.362,24.97) 19.878,24.465 cw(c19.377,24.979) 19.367,24.262 18.077,24.262 cw(c18.074,24.875) 17.643,24.44 cw(c18.002,24.873) 17.442,24.821 17.442,31.2 cw(c17.791,31.211) 17.537,31.45 cw(c17.744,31.21) 17.768,31.527
S-GND on Top Layer "TOP_LAYER_S-GND_P316" (solid, remove dead copper, pour order 316): 35.484,48.844 35.484,36.5 42.672,36.5 42.743,19.406 35.484,19.406 35.484,0.695 75.047,0.695 75.047,48.844
NetC9_1 on Top Layer "TOP_LAYER_NETC9_1_P194" (solid, remove dead copper, pour order 194): 53.143,30.247 53.244,30.247 cw(c53.244,29.688) 53.803,29.688 53.803,28.062 ccw(c55.251,28.062) 55.251,26.615 73.538,26.615 cw(c73.538,25.192) 74.961,25.192 74.961,2.607 cw(c73.04,2.607) 73.04,0.686 50.785,0.686 cw(c50.785,1.529) 49.942,1.529 49.942,21.662 cw(c50.323,21.662) 50.323,22.043 ccw(c50.323,22.271) 50.552,22.271 50.552,24.811 ccw(c50.171,24.811) 50.171,25.192 49.968,25.192 cw(c49.968,25.649) 49.51,25.649 49.51,27.141 cw(c50.069,27.141) 50.069,27.7 50.233,27.7 ccw(c50.233,28.094) 50.628,28.094 50.628,29.713 cw(c51.187,29.713) 51.187,30.272
NetR15_1 on Top Layer "TOP_LAYER_NETR15_1_P310" (solid, remove dead copper, pour order 310): 42.562,22.678 cw(c42.562,22.373) 42.867,22.373 42.867,22.289 ccw(c43.317,22.289) 43.317,21.839 44.799,21.839 cw(c44.799,21.649) 44.989,21.649 44.989,20.798 cw(c44.862,20.798) 44.862,20.671 40.43,20.671 cw(c40.43,21.116) 39.985,21.116 39.985,22.317 cw(c40.345,22.317) 40.345,22.678
NetR12_1 on Top Layer "TOP_LAYER_NETR12_1_P306" (solid, remove dead copper, pour order 306): 44.438,27.656 cw(c44.438,27.199) 44.895,27.199 44.895,26.292 cw(c44.786,26.292) 44.786,26.183 43.11,26.183 ccw(c43.11,25.954) 42.881,25.954 cw(c42.678,25.954) 42.678,25.751 40.29,25.751 cw(c40.29,26.081) 39.96,26.081 39.96,27.351 cw(c40.265,27.351) 40.265,27.656
NetC6_1 on Top Layer "TOP_LAYER_NETC6_1_P276" (solid, remove dead copper, pour order 276): 51.187,31.695 ccw(c51.695,31.695) 51.695,31.187 52.521,31.187 ccw(c52.521,31.706) 53.041,31.706 53.041,33.219 cw(c53.549,33.219) 53.549,33.727 ccw(c53.555,34.254) 54.082,34.248 54.082,34.666 cw(c54.971,34.666) 54.971,35.555 73.538,35.555 ccw(c73.538,37.019) 75.002,37.019 75.002,46.824 ccw(c73.014,46.823) 73.015,48.811 52.86,48.811 ccw(c52.858,47.14) 51.187,47.138
NetC12_1 on Top Layer "TOP_LAYER_NETC12_1_P262" (solid, remove dead copper, pour order 262): 50.933,37.816 cw(c50.603,37.816) 50.603,37.486 47.51,37.486 cw(c47.508,37.872) 47.174,38.063 47.174,39.384 cw(c47.529,39.188) 47.529,39.594 50.577,39.594 cw(c50.577,39.238) 50.933,39.238
NetC12_2 on Top Layer "TOP_LAYER_NETC12_2_P256" (solid, remove dead copper, pour order 256): 49.663,33.727 cw(c49.155,33.727) 49.155,33.219 45.878,33.219 cw(c45.878,33.752) 45.345,33.752 45.345,39.09 cw(c45.853,39.09) 45.853,39.598 46.433,39.598 cw(c46.433,39.162) 46.869,39.162 46.869,37.537 ccw(c47.377,37.537) 47.377,37.029 49.079,37.029 cw(c49.079,36.444) 49.663,36.444
NetR14_1 on Top Layer "TOP_LAYER_NETR14_1_P236" (solid, remove dead copper, pour order 236): 42.899,28.479 cw(c42.683,28.479) 42.683,28.263 38.644,28.263 cw(c38.644,28.689) 38.218,28.689 38.218,29.741 cw(c38.657,29.741) 38.657,30.179 42.691,30.179 cw(c42.691,29.972) 42.899,29.972
NetR14_2 on Top Layer "TOP_LAYER_NETR14_2_P232" (solid, remove dead copper, pour order 232): 42.754,23.225 38.627,23.225 cw(c38.627,23.652) 38.2,23.652 38.2,24.703 cw(c38.639,24.703) 38.639,25.142 42.754,25.142
NetR13_1 on Top Layer "TOP_LAYER_NETR13_1_P106" (solid, pour order 106): 44.367,32.685 cw(c44.436,32.233) 44.889,32.291 44.889,31.035 cw(c44.642,31.035) 44.837,30.882 cw(c44.544,31.155) 44.557,30.755 40.408,30.755 cw(c40.408,31.102) 40.163,30.856 cw(c40.225,30.918) 40.138,30.918 40.138,32.533 cw(c40.385,32.456) 40.265,32.685
NetR11_1 on Top Layer "TOP_LAYER_NETR11_1_P222" (solid, pour order 222): 44.461,35.154 cw(c44.461,34.697) 44.913,34.768 44.913,33.584 cw(c44.544,33.576) 44.81,33.32 cw(c44.565,33.562) 44.583,33.219 40.434,33.219 cw(c40.434,33.565) 40.189,33.32 cw(c40.25,33.382) 40.163,33.381 40.163,34.997 cw(c40.411,34.919) 40.301,35.154
GND on Bottom Layer "BOTTOM_LAYER_GND_P358" (solid, remove dead copper, pour order 358): 32.527,48.875 32.527,36.505 24.932,36.505 24.917,19.406 32.487,19.406 32.487,0.691 0.726,0.691 0.726,48.875
NetR9_2 on Bottom Layer "BOTTOM_LAYER_NETR9_2_P354" (solid, remove dead copper, pour order 354): 27.696,25.481 cw(c27.417,25.456) 27.442,25.177 27.442,23.78 ccw(c27.95,23.78) 27.95,23.272 28.991,23.272 ccw(c28.991,23.754) 29.474,23.754 29.474,26.261 ccw(c29.238,26.261) 29.238,26.497 27.848,26.497 ccw(c27.848,26.345) 27.696,26.345
NetR9_1 on Bottom Layer "BOTTOM_LAYER_NETR9_1_P352" (solid, remove dead copper, pour order 352): 27.472,28.275 27.548,28.275 cw(c27.548,28.098) 27.726,28.098 27.726,27.133 ccw(c27.98,27.133) 27.98,26.878 29.265,26.878 ccw(c29.264,27.132) 29.518,27.132 29.518,29.836 ccw(c29.174,29.836) 29.174,30.18 27.701,30.18 ccw(c27.701,29.952) 27.472,29.952
S-GND on Bottom Layer "BOTTOM_LAYER_S-GND_P324" (solid, pour order 324): 35.36,48.844 75.047,48.844 75.047,0.695 35.36,0.695 35.36,19.406 42.672,19.406 42.672,36.5 35.36,36.5
no net on Bottom Layer "BOTTOM_LAYER_NONET_P198" (solid, remove dead copper, pour order 198): 43.883,25.599 46.462,25.599 cw(c46.535,25.262) 46.873,25.334 ccw(c47.279,25.334) 47.279,24.928 47.889,24.928 cw(c47.889,24.42) 48.397,24.42 48.397,22.932 cw(c47.473,23.126) 47.279,22.203 44.126,22.203 cw(c43.996,22.882) 43.317,22.752 43.317,25.032 cw(c43.883,25.032)
NetR14_1 on Bottom Layer "BOTTOM_LAYER_NETR14_1_P244" (solid, remove dead copper, pour order 244): 39.757,28.266 39.681,28.266 ccw(c39.681,28.088) 39.503,28.088 39.503,27.123 cw(c39.249,27.123) 39.249,26.869 37.964,26.869 cw(c37.965,27.123) 37.711,27.123 37.711,29.827 cw(c38.055,29.827) 38.055,30.171 39.528,30.171 cw(c39.528,29.942) 39.757,29.942
NetR14_2 on Bottom Layer "BOTTOM_LAYER_NETR14_2_P242" (solid, remove dead copper, pour order 242): 39.503,25.446 ccw(c39.782,25.421) 39.757,25.141 39.757,23.744 cw(c39.249,23.744) 39.249,23.236 38.207,23.236 cw(c38.207,23.719) 37.725,23.719 37.725,26.226 cw(c37.961,26.226) 37.961,26.462 39.35,26.462 cw(c39.35,26.31) 39.503,26.31

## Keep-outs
Keep-Out Layer:
  text ".Layer_Name" at 14.656,-21.806 h1.52

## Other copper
Top Layer:
  region: 9.097,28.196
  region: 9.097,28.196
  region: 12.858,30.475
  text ".Layer_Name" at 14.656,-21.806 h1.52
Bottom Layer:
  text ".Layer_Name" at 14.656,-21.806 h1.52

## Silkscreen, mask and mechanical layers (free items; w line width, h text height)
Top Overlay:
  text "PMP30817_RevC" at 2.464,2.667 h2.7
  text ".Layer_Name" at 14.656,-21.806 h0.64
Bottom Overlay:
  text ".Layer_Name" at 14.656,-21.806 h1.52
Top Paste:
  text ".Layer_Name" at 14.656,-21.806 h1.52
Bottom Paste:
  text ".Layer_Name" at 14.656,-21.806 h1.52
Top Solder:
  text ".Layer_Name" at 14.656,-21.806 h1.52
  text ".Layer_Name" at 14.656,-21.806 h1.52
Bottom Solder:
  text ".Layer_Name" at 14.656,-21.806 h1.52
Drill Guide:
  text ".Layer_Name" at 14.656,-21.806 h1.52
M1 Board Outline:
  the board outline again, w0.254
  text ".Layer_Name" at 14.656,-21.806 h1.52
M2 Board Dimensions:
  rectangle: 0,-6.985 3.175,-3.81
  rectangle: 3.175,-10.16 12.7,-6.985
  lines w0.178: 0,-6.985 25.4,-6.985 ; 3.175,-10.16 3.175,-3.81 ; 6.35,-10.16 6.35,-3.81 ; 12.7,-10.16 12.7,-3.81 ; 19.05,-10.16 19.05,-3.81 ; 0,-10.16 25.4,-10.16 25.4,-3.81 0,-3.81 0,-10.16
  text ".Layer_Name" at 14.656,-21.806 h1.52
M3 3D STEP Top:
  text ".Layer_Name" at 14.656,-21.806 h1.52
M4 3D STEP Bottom:
  text ".Layer_Name" at 14.656,-21.806 h1.52
M5 Assembly Top:
  lines w0.254: -7.417,-23.626 160.223,-23.626 ; -7.417,-18.462 160.274,-18.462 ; -7.417,-13.297 -7.417,-28.791 94.31,-28.791 160.274,-28.791 160.274,-13.297 -7.404,-13.297 -7.404,-28.791 32.614,-28.791 ; 55.194,-28.791 55.194,-13.297 ; 87.376,-18.462 87.376,-13.297 ; 108.712,-18.462 108.712,-13.297 ; 124.511,-28.956 124.511,-23.804
  text "COMPONENTS MARKED 'DNP' SHOULD NOT BE POPULATED." at 29.299,-8.09 h1.52
  text "ASSEMBLY VARIANT:" at 29.286,-11.024 h1.52
  text ".VariantName" at 55.601,-11.024 h1.52
  text "PCB VIEWED FROM TOP SIDE" at -5.804,-16.654 h1.52
  text "BOARD #:" at 57.099,-16.654 h1.52
  text ".PRJ_Number" at 70.955,-16.654 h1.52
  text "REV:" at 92.405,-16.654 h1.52
  text ".PCB_Rev" at 99.809,-16.654 h1.52
  text "SVN REV:" at 113.69,-16.654 h1.52
  text ".VersionControl_RevNumber" at 126.543,-16.654 h1.52
  text "TID #:" at 57.099,-21.819 h1.52
  text ".TID" at 70.955,-21.819 h1.52
  text "PLOT NAME =" at -5.804,-27.034 h1.52
  text ".plot_File_Name" at 14.656,-27.034 h1.52
  text "GENERATED    :" at 57.15,-27.034 h1.52
  text ".Print_Date" at 79.235,-27.034 h1.52
  text ".Print_Time" at 97.752,-27.034 h1.52
  text "TEXAS INSTRUMENTS" at 129.87,-27.034 h1.52
M6 Assembly Bottom:
  lines w0.254: -7.429,-18.474 160.261,-18.474 ; -7.379,-23.639 160.261,-23.639 ; 28.334,-28.969 28.334,-23.817 ; 44.133,-18.474 44.133,-13.31 ; 65.468,-18.474 65.468,-13.31 ; 97.65,-28.804 97.65,-13.31 ; 120.231,-28.804 160.249,-28.804 160.249,-13.31 -7.429,-13.31 -7.429,-28.804 58.534,-28.804 160.261,-28.804 160.261,-13.31
  text "COMPONENTS MARKED 'DNP' SHOULD NOT BE POPULATED." at 154.991,-8.077 h1.52
  text ".VariantName" at 128.473,-11.024 h1.52
  text "ASSEMBLY VARIANT:" at 154.864,-11.024 h1.52
  text ".VersionControl_RevNumber" at 26.302,-16.667 h1.52
  text "SVN REV:" at 39.154,-16.667 h1.52
  text ".PCB_Rev" at 53.035,-16.667 h1.52
  text "REV:" at 60.439,-16.667 h1.52
  text ".PRJ_Number" at 81.89,-16.667 h1.52
  text "BOARD #:" at 95.745,-16.667 h1.52
  text "PCB VIEWED FROM BOTTOM SIDE" at 158.648,-16.667 h1.52
  text ".TID" at 81.89,-21.831 h1.52
  text "TID #:" at 95.745,-21.831 h1.52
  text "TEXAS INSTRUMENTS" at 22.974,-27.047 h1.52
  text ".Print_Time" at 55.093,-27.047 h1.52
  text ".Print_Date" at 73.609,-27.047 h1.52
  text "GENERATED    :" at 95.694,-27.047 h1.52
  text ".plot_File_Name" at 138.189,-27.047 h1.52
  text "PLOT NAME =" at 158.648,-27.047 h1.52
M9 Title Sheet:
  drawing of 57 lines, arcs and shapes, not listed
  text "1" at 18.792,204.127 h1.78
  text "2" at 82.182,204.127 h1.78
  text "3" at 145.411,204.127 h1.78
  text "4" at 209.08,204.127 h1.78
  text "5" at 272.555,204.127 h1.78
  text "6" at 336.182,204.127 h1.78
  text "A" at -10.579,175.095 h1.78
  text "A" at 365.341,175.095 h1.78
  text "B" at -10.579,114.643 h1.78
  text "B" at 365.341,114.643 h1.78
  text "C" at -10.579,54.318 h1.78
  text "C" at 365.341,54.318 h1.78
  text "PROJECT TITLE:" at 288.125,7.048 h1.14
  text ".PRJ_Title" at 289.395,3.662 h1.78
  text "DESIGNED FOR:" at 288.125,-0.597 h1.14
  text ".PRJ_Customer" at 289.395,-4.153 h1.78
  text "D" at -10.579,-5.88 h1.78
  text "D" at 365.341,-5.88 h1.78
  text "FILE NAME:" at 288.125,-8.217 h1.14
  text ".PCB_File_Name_No_Path" at 289.395,-11.265 h1.78
  text "Texas Instruments (TI) and/or its licensors do not warrant the accuracy or completeness of this specification" at 161.9,-15.376 h1.14
  text "ENGINEER:" at 288.125,-15.583 h1.14
  text "LAYOUT BY:" at 326.352,-15.583 h1.14
  text "or any information contained therein. TI and/or its licensors do not warrant that this design will meet" at 160.757,-18.237 h1.14
  text ".PRJ_Engineer" at 289.395,-19.52 h1.78
  text ".PCB_Layout" at 327.635,-19.52 h1.78
  text "the specifications, will be suitable for your application or fit for any particular purpose, or will operate in" at 160.757,-21.099 h1.14
  text ".Layer_Name" at 14.656,-21.806 h1.52
  text "ALTIUM DESIGNER VERSION:" at 326.352,-23.457 h1.14
  text "an implementation. TI and/or its licensors do not warrant that the design is production worthy. You should" at 160.757,-23.961 h1.14
  text "completely validate and test your design implementation to confirm the system functionality for your application." at 161.9,-26.822 h1.14
  text ".print_Scale" at 289.395,-26.843 h1.78
  text ".Application_BuildNumber" at 327.635,-26.843 h1.78
  text "1" at 18.792,-32.093 h1.78
  text "2" at 82.182,-32.093 h1.78
  text "3" at 145.411,-32.093 h1.78
  text "4" at 209.08,-32.093 h1.78
  text "5" at 272.555,-32.093 h1.78
  text "6" at 336.182,-32.093 h1.78
M10 Fab Notes:
  lines w0.508: 287.122,163.861 287.122,22.123 363.093,22.123 363.093,163.861
  text ".Layer_Name" at 14.656,-21.806 h1.52
M11 Gerber Information:
  lines w0.254: -7.417,-23.626 160.223,-23.626 ; -7.417,-18.462 160.274,-18.462 ; -7.417,-13.297 -7.417,-28.791 94.31,-28.791 160.274,-28.791 160.274,-13.297 -7.404,-13.297 -7.404,-28.791 32.614,-28.791 ; 55.194,-28.791 55.194,-13.297 ; 87.376,-18.462 87.376,-13.297 ; 108.712,-18.462 108.712,-13.297 ; 124.511,-28.956 124.511,-23.804
  text "ALL ARTWORK VIEWED FROM TOP SIDE" at -5.804,-16.654 h1.52
  text "BOARD #:" at 57.099,-16.654 h1.52
  text ".PRJ_Number" at 70.955,-16.654 h1.52
  text "REV:" at 92.405,-16.654 h1.52
  text ".PCB_Rev" at 99.809,-16.654 h1.52
  text "SVN REV:" at 113.69,-16.654 h1.52
  text ".VersionControl_RevNumber" at 126.543,-16.654 h1.52
  text "LAYER NAME =" at -5.804,-21.806 h1.52
  text "TID #:" at 57.099,-21.819 h1.52
  text ".TID" at 70.955,-21.819 h1.52
  text "PLOT NAME =" at -5.804,-27.034 h1.52
  text ".plot_File_Name" at 14.656,-27.034 h1.52
  text "GENERATED    :" at 57.15,-27.034 h1.52
  text ".Print_Date" at 79.235,-27.034 h1.52
  text ".Print_Time" at 97.752,-27.034 h1.52
  text "TEXAS INSTRUMENTS" at 129.87,-27.034 h1.52
M12 Stackup:
  text ".Layer_Name" at 14.656,-21.806 h1.52
M13 Component Bodies Top:
  text ".Layer_Name" at 14.656,-21.806 h1.52
M14 Component Bodies Bottom:
  text ".Layer_Name" at 14.656,-21.806 h1.52
M15 Courtyards Top:
  text ".Layer_Name" at 14.656,-21.806 h1.52
M16 Courtyards Bottom:
  text ".Layer_Name" at 14.656,-21.806 h1.52
Drill Drawing:
  text ".Layer_Name" at 14.656,-21.806 h1.52
M17 Embedded Cavity:
  text ".Layer_Name" at 14.656,-21.806 h1.52
M18 Embedded Assembly:
  text ".Layer_Name" at 14.656,-21.806 h1.52
M19 Embedded Keepout:
  text ".Layer_Name" at 14.656,-21.806 h1.52

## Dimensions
0,-10.16 to 25.4,-10.16 on M2 Board Dimensions
0,0 to 75.768,0 on M2 Board Dimensions
0,0 to 0,49.682 on M2 Board Dimensions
